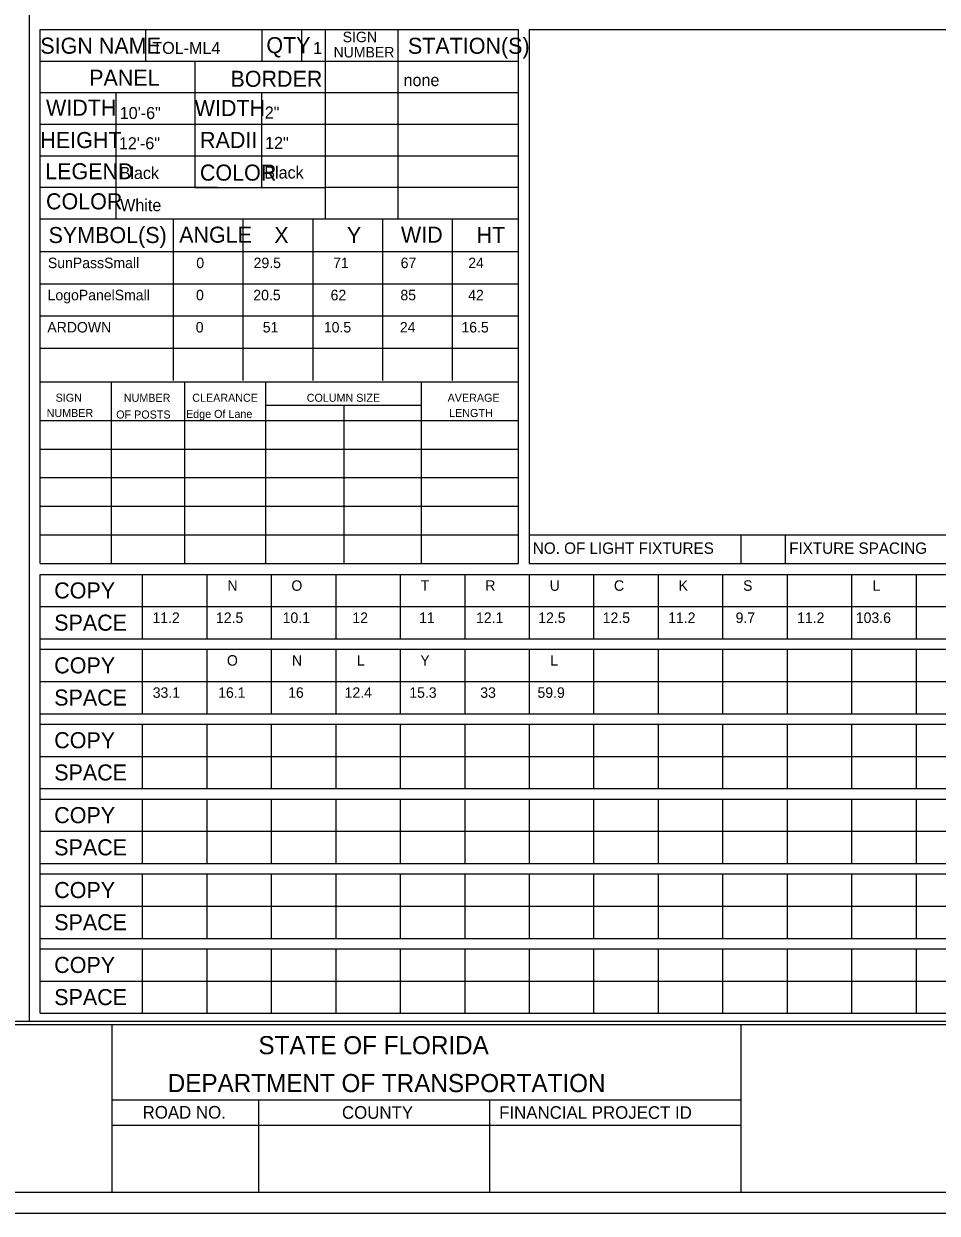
# Model space of a CAD drawing. Extents: x 119523 to 121850, y -23542 to -19972.
# Drawn here: x 120684 to 121298, y -23523 to -22723 of the extents above; entities that cross this region are included whole.
import ezdxf

# ---------------------------------------------------------------- set-up
doc = ezdxf.new("R2010")
doc.units = 0
for name, color, linetype in [('GSDims', 7, 'Continuous'), ('PlotBorder_dp', 7, 'Continuous'), ('SheetBorder_dp', 7, 'Continuous'), ('SheetLines_dp', 7, 'Continuous'), ('SheetLinesMisc2_dp', 7, 'Continuous'), ('TextMinor', 7, 'Continuous'), ('TextMisc', 7, 'Continuous')]:
    doc.layers.add(name, color=color, linetype=linetype)

msp = doc.modelspace()

# ---------------------------------------------------------------- linework, layer by layer
at = {"layer": 'PlotBorder_dp'}
msp.add_lwpolyline([(119522.87, -23522.86), (121850.2, -23522.86), (121850.2, -22027.72), (119522.87, -22027.72)], close=True, dxfattribs=at)
at = {"layer": 'SheetBorder_dp'}
for p, q in [((119600.45, -23395.91), (121772.62, -23395.91)), ((119600.45, -23508.75), (121772.62, -23508.75))]:
    msp.add_line(p, q, dxfattribs=at)
at = {"layer": 'SheetLines_dp'}
for p, q in [((120742.96, -23395.91), (120742.96, -23508.75)), ((121166.11, -23508.75), (121166.11, -23395.91)), ((120742.96, -23446.69), (121166.11, -23446.69)), ((120841.69, -23446.69), (120841.69, -23508.75)), ((120996.85, -23446.69), (120996.85, -23508.75)), ((120742.96, -23463.61), (121166.11, -23463.61))]:
    msp.add_line(p, q, dxfattribs=at)
at = {"layer": 'SheetLinesMisc2_dp'}
for p, q in [((120687.5, -22045.17), (120687.5, -23393.68)), ((120694.93, -23086.05), (120694.93, -22727.17)), ((120694.93, -22727.17), (121016.13, -22727.17)), ((120765.73, -22727.17), (120765.73, -22748.36)), ((120843.81, -22727.17), (120843.81, -22748.36)), ((120870.48, -22727.17), (120870.48, -22748.36)), ((120886.37, -22727.17), (120886.37, -22854.36)), ((120935.25, -22727.17), (120935.25, -22854.36)), ((121016.13, -22727.17), (121016.13, -23086.05)), ((121023.51, -22727.16), (121760.29, -22727.16)), ((121023.51, -22727.16), (121023.51, -23085.53)), ((120694.93, -22748.36), (121016.13, -22748.36)), ((120798.73, -22748.36), (120798.73, -22833.38)), ((120694.93, -22769.56), (121016.13, -22769.56)), ((120745.69, -22769.56), (120745.69, -22854.36)), ((120843.53, -22769.79), (120843.53, -22833.38)), ((120694.93, -22790.76), (121016.13, -22790.76)), ((120694.93, -22811.96), (121016.13, -22811.96)), ((120694.93, -22833.16), (120814.05, -22833.16)), ((120798.73, -22833.38), (120886.37, -22833.38)), ((120886.37, -22833.16), (121016.13, -22833.16)), ((120694.93, -22854.36), (121016.13, -22854.36)), ((120784.13, -22854.77), (120784.13, -22963)), ((120831.06, -22854.77), (120831.06, -22963)), ((120878, -22854.77), (120878, -22963)), ((120924.93, -22854.77), (120924.93, -22963)), ((120971.86, -22854.77), (120971.86, -22963)), ((120695, -22876.42), (121016.13, -22876.42)), ((120695, -22898.07), (121016.13, -22898.07)), ((120695, -22919.71), (121016.13, -22919.71)), ((120695, -22941.35), (121016.13, -22941.35)), ((120694.93, -22964.04), (121016.13, -22964.04)), ((120742.59, -22964.04), (120742.59, -23086.05)), ((120791.86, -22964.04), (120791.86, -23086.05)), ((120846.25, -22964.04), (120846.25, -23086.05)), ((120951, -22964.04), (120951, -23086.05)), ((120846.25, -22979.55), (120950.93, -22979.55)), ((120898.84, -22979.55), (120898.84, -23086.05)), ((120694.93, -22989.91), (121016.13, -22989.91)), ((120694.93, -23009.13), (121016.13, -23009.13)), ((120694.93, -23028.36), (121016.13, -23028.36)), ((120694.93, -23047.59), (121016.13, -23047.59)), ((120694.93, -23066.82), (121016.13, -23066.82)), ((121023.51, -23066.81), (121760.29, -23066.81)), ((121165.82, -23066.81), (121165.82, -23086.04)), ((121195.64, -23066.81), (121195.64, -23086.04)), ((120694.93, -23086.05), (121016.13, -23086.05)), ((121023.51, -23085.53), (121023.51, -23086.02)), ((121023.51, -23086.04), (121760.29, -23086.04)), ((120694.9, -23093.43), (121760.29, -23093.43)), ((120694.9, -23388.43), (120694.9, -23093.43)), ((120763.48, -23093.43), (120763.48, -23136.72)), ((120806.83, -23093.43), (120806.83, -23136.72)), ((120850.15, -23093.43), (120850.15, -23136.72)), ((120893.49, -23093.43), (120893.49, -23136.72)), ((120936.85, -23093.43), (120936.85, -23136.72)), ((120980.18, -23093.43), (120980.18, -23136.72)), ((121023.51, -23093.43), (121023.51, -23136.72)), ((121066.86, -23093.43), (121066.86, -23136.72)), ((121110.2, -23093.43), (121110.2, -23136.72)), ((121153.54, -23093.43), (121153.54, -23136.72)), ((121196.89, -23093.43), (121196.89, -23136.72)), ((121240.21, -23093.43), (121240.21, -23136.72)), ((121283.56, -23093.43), (121283.56, -23136.72)), ((120694.9, -23115.06), (121760.29, -23115.06)), ((120694.9, -23136.72), (121760.29, -23136.72)), ((120694.9, -23143.78), (121760.29, -23143.78)), ((120763.48, -23143.78), (120763.48, -23187.06)), ((120806.83, -23143.78), (120806.83, -23187.06)), ((120850.15, -23143.78), (120850.15, -23187.06)), ((120893.49, -23143.78), (120893.49, -23187.06)), ((120936.85, -23143.78), (120936.85, -23187.06)), ((120980.18, -23143.78), (120980.18, -23187.06)), ((121023.51, -23143.78), (121023.51, -23187.06)), ((121066.86, -23143.78), (121066.86, -23187.06)), ((121110.2, -23143.78), (121110.2, -23187.06)), ((121153.54, -23143.78), (121153.54, -23187.06)), ((121196.89, -23143.78), (121196.89, -23187.06)), ((121240.21, -23143.78), (121240.21, -23187.06)), ((121283.56, -23143.78), (121283.56, -23187.06)), ((120694.9, -23165.42), (121760.29, -23165.42)), ((120694.9, -23187.06), (121760.29, -23187.06)), ((120694.9, -23194.12), (121760.29, -23194.12)), ((120763.48, -23194.12), (120763.48, -23237.41)), ((120806.83, -23194.12), (120806.83, -23237.41)), ((120850.15, -23194.12), (120850.15, -23237.41)), ((120893.49, -23194.12), (120893.49, -23237.41)), ((120936.85, -23194.12), (120936.85, -23237.41)), ((120980.18, -23194.12), (120980.18, -23237.41)), ((121023.51, -23194.12), (121023.51, -23237.41)), ((121066.86, -23194.12), (121066.86, -23237.41)), ((121110.2, -23194.12), (121110.2, -23237.41)), ((121153.54, -23194.12), (121153.54, -23237.41)), ((121196.89, -23194.12), (121196.89, -23237.41)), ((121240.21, -23194.12), (121240.21, -23237.41)), ((121283.56, -23194.12), (121283.56, -23237.41)), ((120694.9, -23215.76), (121760.29, -23215.76)), ((120694.9, -23237.41), (121760.29, -23237.41)), ((120694.9, -23244.46), (121760.29, -23244.46)), ((120763.48, -23244.46), (120763.48, -23287.75)), ((120806.83, -23244.46), (120806.83, -23287.75)), ((120850.15, -23244.46), (120850.15, -23287.75)), ((120893.49, -23244.46), (120893.49, -23287.75)), ((120936.85, -23244.46), (120936.85, -23287.75)), ((120980.18, -23244.46), (120980.18, -23287.75)), ((121023.51, -23244.46), (121023.51, -23287.75)), ((121066.86, -23244.46), (121066.86, -23287.75)), ((121110.2, -23244.46), (121110.2, -23287.75)), ((121153.54, -23244.46), (121153.54, -23287.75)), ((121196.89, -23244.46), (121196.89, -23287.75)), ((121240.21, -23244.46), (121240.21, -23287.75)), ((121283.56, -23244.46), (121283.56, -23287.75)), ((120694.9, -23266.09), (121760.29, -23266.09)), ((120694.9, -23287.75), (121760.29, -23287.75)), ((120694.9, -23294.81), (121760.29, -23294.81)), ((120763.48, -23294.81), (120763.48, -23338.09)), ((120806.83, -23294.81), (120806.83, -23338.09)), ((120850.15, -23294.81), (120850.15, -23338.09)), ((120893.49, -23294.81), (120893.49, -23338.09)), ((120936.85, -23294.81), (120936.85, -23338.09)), ((120980.18, -23294.81), (120980.18, -23338.09)), ((121023.51, -23294.81), (121023.51, -23338.09)), ((121066.86, -23294.81), (121066.86, -23338.09)), ((121110.2, -23294.81), (121110.2, -23338.09)), ((121153.54, -23294.81), (121153.54, -23338.09)), ((121196.89, -23294.81), (121196.89, -23338.09)), ((121240.21, -23294.81), (121240.21, -23338.09)), ((121283.56, -23294.81), (121283.56, -23338.09)), ((120694.9, -23316.46), (121760.29, -23316.46)), ((120694.9, -23338.09), (121760.29, -23338.09)), ((120694.9, -23345.15), (121760.29, -23345.15)), ((120763.48, -23345.15), (120763.48, -23388.43)), ((120806.83, -23345.15), (120806.83, -23388.43)), ((120850.15, -23345.15), (120850.15, -23388.43)), ((120893.49, -23345.15), (120893.49, -23388.43)), ((120936.85, -23345.15), (120936.85, -23388.43)), ((120980.18, -23345.15), (120980.18, -23388.43)), ((121023.51, -23345.15), (121023.51, -23388.43)), ((121066.86, -23345.15), (121066.86, -23388.43)), ((121110.2, -23345.15), (121110.2, -23388.43)), ((121153.54, -23345.15), (121153.54, -23388.43)), ((121196.89, -23345.15), (121196.89, -23388.43)), ((121240.21, -23345.15), (121240.21, -23388.43)), ((121283.56, -23345.15), (121283.56, -23388.43)), ((120694.9, -23366.79), (121760.29, -23366.79)), ((119604.34, -23393.68), (121770.65, -23393.68)), ((120694.9, -23388.43), (121760.29, -23388.43))]:
    msp.add_line(p, q, dxfattribs=at)

# ---------------------------------------------------------------- texts
at = {"layer": 'GSDims'}
for s, height, p in [('TOL-ML4', 8.095, (120770.23, -22743.55)), ('1', 8.09, (120878.28, -22743.57)), ('none', 8.095, (120939.1, -22765.17)), ('10\'-6"', 8.095, (120748.33, -22787.31)), ('2"', 8.095, (120845.8, -22787.01)), ('12\'-6"', 8.095, (120747.78, -22807.65)), ('12"', 8.095, (120846.02, -22807.42)), ('Black', 8.095, (120748.24, -22827.61)), ('Black', 8.095, (120845.47, -22827.29)), ('White', 8.095, (120748.6, -22849.25)), ('SunPassSmall', 7.0546, (120700.02, -22887.54)), ('0', 7.05, (120799.78, -22887.54)), ('29.5', 7.055, (120838.3, -22887.54)), ('71', 7.055, (120891.76, -22887.54)), ('67', 7.055, (120937.15, -22887.54)), ('24', 7.055, (120982.56, -22887.54)), ('LogoPanelSmall', 7.0546, (120699.83, -22909.17)), ('0', 7.05, (120799.59, -22909.17)), ('20.5', 7.055, (120838.1, -22909.17)), ('62', 7.055, (120890.05, -22909.17)), ('85', 7.055, (120936.96, -22909.17)), ('42', 7.055, (120982.54, -22909.17)), ('ARDOWN', 7.055, (120699.64, -22930.81)), ('0', 7.05, (120799.4, -22930.81)), ('10.5', 7.055, (120885.49, -22930.81)), ('24', 7.055, (120936.59, -22930.81)), ('16.5', 7.055, (120977.98, -22930.81)), ('51', 7.055, (120844.46, -22930.81)), ('N', 7.05, (120820.7, -23104.45)), ('O', 7.05, (120863.69, -23104.45)), ('T', 7.05, (120950.68, -23104.45)), ('R', 7.05, (120994.01, -23104.45)), ('U', 7.05, (121037.34, -23104.45)), ('C', 7.05, (121080.5, -23104.45)), ('K', 7.05, (121123.99, -23104.45)), ('S', 7.05, (121167.32, -23104.45)), ('L', 7.05, (121254.31, -23104.45)), ('11.2', 7.055, (120770.32, -23126.08)), ('12.5', 7.055, (120812.98, -23126.08)), ('10.1', 7.055, (120857.81, -23126.08)), ('12', 7.055, (120904.67, -23126.08)), ('11', 7.055, (120949.51, -23126.08)), ('12.1', 7.055, (120987.8, -23126.08)), ('12.5', 7.055, (121029.61, -23126.08)), ('12.5', 7.055, (121072.94, -23126.08)), ('11.2', 7.055, (121116.94, -23126.08)), ('9.7', 7.055, (121162.28, -23126.08)), ('11.2', 7.055, (121203.59, -23126.08)), ('103.6', 7.055, (121243.06, -23126.08)), ('O', 7.05, (120820.37, -23154.77)), ('N', 7.05, (120864.03, -23154.77)), ('L', 7.05, (120907.69, -23154.77)), ('Y', 7.05, (120950.35, -23154.77)), ('L', 7.05, (121037.67, -23154.77)), ('33.1', 7.055, (120770.49, -23176.4)), ('16.1', 7.055, (120814.49, -23176.4)), ('16', 7.055, (120861.51, -23176.4)), ('12.4', 7.055, (120899.46, -23176.4)), ('15.3', 7.055, (120942.96, -23176.4)), ('33', 7.055, (120990.65, -23176.4)), ('59.9', 7.055, (121029.11, -23176.4))]:
    msp.add_text(s, height=height, dxfattribs=at).set_placement(p)
at = {"layer": 'TextMinor'}
for s, height, p in [('SIGN', 7.058, (120898.17, -22735.66)), ('SIGN NAME', 10.799, (120694.93, -22743.4)), ('QTY', 10.799, (120846.88, -22743.04)), ('NUMBER', 7.058, (120892.03, -22745.93)), ('STATION(S)', 10.799, (120941.99, -22743.46)), ('PANEL', 10.799, (120727.76, -22764.93)), ('BORDER', 10.799, (120822.74, -22765.66)), ('WIDTH', 10.799, (120698.74, -22785.11)), ('WIDTH', 10.799, (120798.73, -22785.33)), ('HEIGHT', 10.799, (120694.93, -22806.84)), ('RADII', 10.799, (120802.28, -22806.8)), ('LEGEND', 10.799, (120698.17, -22827.81)), ('COLOR', 10.799, (120802.2, -22828.72)), ('COLOR', 10.799, (120698.74, -22848.03)), ('SYMBOL(S)', 10.799, (120700.46, -22870.69)), ('ANGLE', 10.799, (120788.26, -22870.47)), ('WID', 10.799, (120937.32, -22870.47)), ('X', 10.8, (120852.18, -22870.69)), ('Y', 10.8, (120900.98, -22870.69)), ('HT', 10.799, (120988.2, -22870.67)), ('SIGN', 5.4, (120705.22, -22977.35)), ('NUMBER', 5.4, (120751.06, -22977.42)), ('CLEARANCE', 5.4, (120797.04, -22977.38)), ('COLUMN SIZE', 5.3996, (120873.99, -22977.38)), ('AVERAGE', 5.4, (120968.7, -22977.38)), ('NUMBER', 5.4, (120699.17, -22987.62)), ('OF POSTS', 5.4, (120745.96, -22988.64)), ('Edge Of Lane', 5.3996, (120792.88, -22988.25)), ('LENGTH', 5.4, (120969.72, -22987.62)), ('NO. OF LIGHT FIXTURES', 7.6529, (121025.99, -23079.6)), ('FIXTURE SPACING', 7.6529, (121198.29, -23079.6)), ('COPY', 10.799, (120704.26, -23109.61)), ('SPACE', 10.799, (120704.26, -23131.26)), ('COPY', 10.799, (120704.26, -23159.98)), ('SPACE', 10.799, (120704.26, -23181.62)), ('COPY', 10.799, (120704.26, -23210.3)), ('SPACE', 10.799, (120704.26, -23231.95)), ('COPY', 10.799, (120704.26, -23260.66)), ('SPACE', 10.799, (120704.26, -23282.29)), ('COPY', 10.799, (120704.26, -23311.01)), ('SPACE', 10.799, (120704.26, -23332.65)), ('COPY', 10.799, (120704.26, -23361.35)), ('SPACE', 10.799, (120704.26, -23382.98))]:
    msp.add_text(s, height=height, dxfattribs=at).set_placement(p)
at = {"layer": 'TextMisc'}
for s, height, p in [('STATE OF FLORIDA', 12.1867, (120841.54, -23415.98)), ('DEPARTMENT OF TRANSPORTATION', 12.1867, (120780.57, -23441.45)), ('ROAD NO.', 8.463, (120763.69, -23459.24)), ('COUNTY', 8.463, (120897.69, -23459.38)), ('FINANCIAL PROJECT ID', 8.463, (121003.33, -23459.38))]:
    msp.add_text(s, height=height, dxfattribs=at).set_placement(p)

doc.saveas('drawing.dxf')
